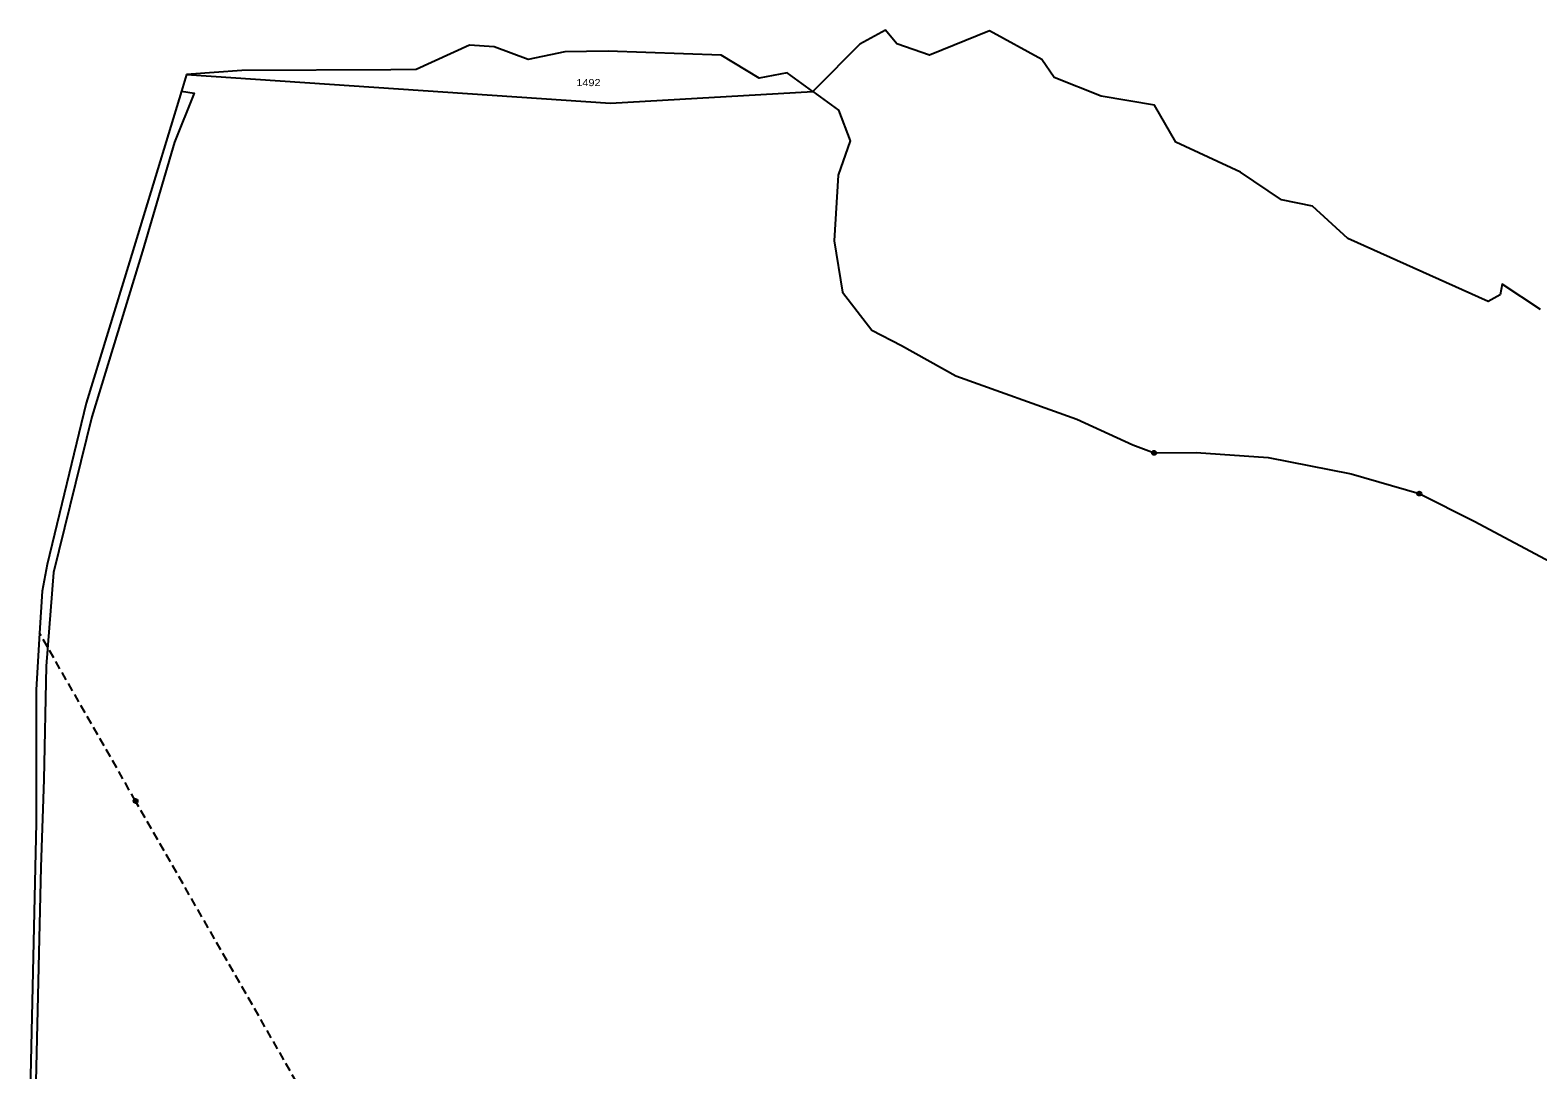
# Model space of a CAD drawing. Extents: x -872229 to -869198, y -1075981 to -1074329.
# Drawn here: x -872228.8 to -871865, y -1074906.2 to -1074655.5 of the extents above; entities that cross this region are included whole.
import ezdxf

# ---------------------------------------------------------------- set-up
doc = ezdxf.new("R2010")
doc.units = 0
doc.header["$LTSCALE"] = 0.68
doc.linetypes.add('MEDIUM_DASHED', pattern=[4.5, 3, -1.5])
for name, color, linetype, lineweight in [('1', 7, 'Continuous', 25), ('6', 7, 'Continuous', 25), ('8', 7, 'Continuous', 25)]:
    doc.layers.add(name, color=color, linetype=linetype, lineweight=lineweight)
doc.layers.add('2', color=7, linetype='Continuous')

msp = doc.modelspace()

# ---------------------------------------------------------------- linework, layer by layer
at = {"layer": '1'}
msp.add_line((-872191.02, -1074666.24), (-872192.24, -1074670.26), dxfattribs=at)
for points in [[(-871864.39, -1074722.89), (-871873.59, -1074716.74), (-871874.11, -1074719.31), (-871876.98, -1074720.95), (-871910.83, -1074705.76), (-871919.4, -1074697.97), (-871926.89, -1074696.43), (-871936.73, -1074689.76), (-871952.33, -1074682.57), (-871957.54, -1074673.58), (-871970.36, -1074671.42), (-871981.73, -1074666.91), (-871984.71, -1074662.6), (-871997.29, -1074655.72), (-872011.75, -1074661.58), (-872019.63, -1074658.8), (-872022.4, -1074655.52), (-872028.56, -1074658.91), (-872031.23, -1074661.58), (-872036.74, -1074667.1), (-872039.95, -1074670.3)], [(-872039.95, -1074670.3), (-872046.1, -1074665.79), (-872052.87, -1074667.12), (-872062.05, -1074661.58), (-872089.34, -1074660.55), (-872099.8, -1074660.76), (-872108.63, -1074662.6), (-872116.83, -1074659.52), (-872122.78, -1074659.11), (-872135.65, -1074665.03), (-872141.78, -1074665.06), (-872177.71, -1074665.23), (-872191.02, -1074666.24)], [(-872191.02, -1074666.24), (-872088.78, -1074673.15), (-872039.95, -1074670.3)], [(-872192.24, -1074670.26), (-872204.77, -1074711.42), (-872215.23, -1074745.5), (-872224.64, -1074784.41), (-872225.88, -1074790.78), (-872226.49, -1074800.94), (-872227.31, -1074814.6), (-872227.32, -1074846.71), (-872228.76, -1074911.36), (-872197.72, -1074989.94)], [(-872192.24, -1074670.26), (-872189.2, -1074670.7), (-872193.96, -1074682.52), (-872201.67, -1074708.83), (-872213.91, -1074748.73), (-872223.11, -1074786.33), (-872224.92, -1074808.89), (-872225.49, -1074836.22), (-872226.17, -1074857.35), (-872227.42, -1074909.07), (-872221.41, -1074925.13), (-872203.26, -1074970.76), (-872195.18, -1074989.21), (-872176.56, -1075010.03), (-872170.02, -1075024.01), (-872159.08, -1075049.04), (-872156.25, -1075055.62), (-872144.83, -1075089.41), (-872110.79, -1075148.09)], [(-872039.95, -1074670.3), (-872033.72, -1074674.81), (-872030.92, -1074682.19), (-872033.83, -1074690.5), (-872034.76, -1074706.29), (-872032.79, -1074718.71), (-872025.73, -1074727.85), (-872018.58, -1074731.54), (-872005.47, -1074738.91), (-871976.27, -1074749.31), (-871962.71, -1074755.49), (-871957.59, -1074757.47), (-871947.45, -1074757.37), (-871930.06, -1074758.6), (-871910.06, -1074762.54), (-871893.62, -1074767.28), (-871880.39, -1074773.91), (-871852.19, -1074788.97)]]:
    msp.add_lwpolyline(points, dxfattribs=at)
at = {"layer": '6', "linetype": 'MEDIUM_DASHED'}
msp.add_line((-872203.32, -1074841.42), (-872226.49, -1074800.94), dxfattribs=at)
msp.add_lwpolyline([(-872128.23, -1074972.65), (-872162.98, -1074911.84), (-872203.32, -1074841.42)], dxfattribs=at)
at = {"layer": '6'}
for radius in [0.5, 0.4, 0.3, 0.2, 0.1]:
    msp.add_circle((-872203.3234, -1074841.4199), radius, dxfattribs=at)
at = {"layer": '8'}
for centre, radius in [((-871957.59, -1074757.4699), 0.5), ((-871957.59, -1074757.4699), 0.0303), ((-871893.62, -1074767.2799), 0.5), ((-871893.62, -1074767.2799), 0.0303)]:
    msp.add_circle(centre, radius, dxfattribs=at)

# ---------------------------------------------------------------- texts
at = {"layer": '2', "width": 1.15}
msp.add_text('1492', height=1.7, dxfattribs=at).set_placement((-872096.97, -1074669.02))

doc.saveas('drawing.dxf')
